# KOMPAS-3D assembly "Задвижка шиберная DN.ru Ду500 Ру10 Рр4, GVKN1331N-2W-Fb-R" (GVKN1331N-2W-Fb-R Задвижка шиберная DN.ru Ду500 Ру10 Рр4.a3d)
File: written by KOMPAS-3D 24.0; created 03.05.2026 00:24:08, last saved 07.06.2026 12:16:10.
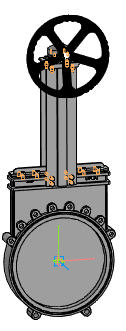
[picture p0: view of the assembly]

Document properties: Автор: DN.ru; Полное имя файла: E:\Работа\Зайцев\АУТСОРС\Даня\GVKN1331N-2W-Fb-R Задвижка шиберная DN.ru Ду400-600 Ру4-6\исходные материалы\DN500\GVKN1331N-2W-Fb-R Задвижка шиберная DN.ru Ду500 Ру10 Рр4.a3d

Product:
- Component [detail]: 1  | designation Деталь  | qty 1  | pos. 1  | Масса: 18.2; Раздел спецификации: Прочие изделия; Примечание: D050-23732; Автор: R2D2; source file: GVKN1331N-2W-Fb-R Задвижка шиберная DN.ru Ду500 Ру10 Рр4.m3d
- Component [detail]: Деталь 2  | qty 1  | pos. 2  | Масса: 13.775591; Автор: mrdid; additional columns: Типовые; source file: Деталь 2 - Деталь 2.m3d
- Part/product: Задвижка шиберная DN.ru Ду500 Ру10 Рр4  | designation GVKN1331N-2W-Fb-R
    Масса: 192
    Раздел спецификации: Прочие изделия
    Примечание: D040-07324

Referenced files in E:\Работа\Зайцев\АУТСОРС\Даня\GVKN1331N-2W-Fb-R Задвижка шиберная DN.ru Ду400-600 Ру4-6\исходные материалы\DN500\: Деталь 2 - Деталь 2.m3d, GVKN1331N-2W-Fb-R Задвижка шиберная DN.ru Ду500 Ру10 Рр4.m3d
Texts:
  GVKN1331N-2W-Fb-R
  Деталь 1
  Деталь 2 Деталь 2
